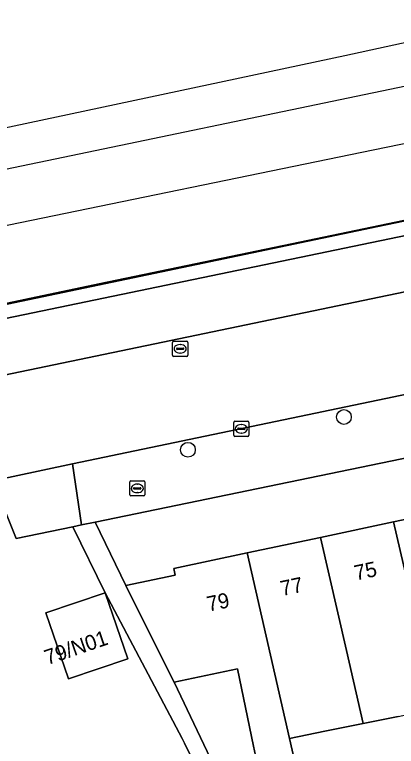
# Model space of a CAD drawing. Extents: x 162989 to 165008, y 383432 to 384338.
# Drawn here: x 163919.28 to 163944.51, y 384116.68 to 384165.09 of the extents above; entities that cross this region are included whole.
import ezdxf

# ---------------------------------------------------------------- set-up
doc = ezdxf.new("R2010")
doc.units = 0
for name, color, linetype in [('IMGEO_Boom', 7, 'Continuous'), ('IMGEO_Brandkraan', 7, 'Continuous'), ('IMGEO_Erf', 7, 'Continuous'), ('IMGEO_Geluidsscherm', 7, 'Continuous'), ('IMGEO_Groenvoorziening', 7, 'Continuous'), ('IMGEO_Haag', 7, 'Continuous'), ('IMGEO_Kolk', 7, 'Continuous'), ('IMGEO_Pand', 7, 'Continuous'), ('IMGEO_Pand_nummerreeks', 7, 'Continuous'), ('IMGEO_Rijbaan_lokaal_gesloten', 7, 'Continuous'), ('IMGEO_Rioolput', 7, 'Continuous'), ('IMGEO_Spoor', 7, 'Continuous'), ('IMGEO_Spoorbaan_halfverhard', 7, 'Continuous'), ('IMGEO_Voetpad_open', 7, 'Continuous')]:
    doc.layers.add(name, color=color, linetype=linetype)

msp = doc.modelspace()

# ---------------------------------------------------------------- linework, layer by layer
at = {"layer": 'IMGEO_Boom'}
for centre in [(163941.046, 384138.472), (163930.735, 384136.302)]:
    msp.add_circle(centre, 0.489, dxfattribs=at)
at = {"layer": 'IMGEO_Brandkraan'}
for p, q in [((163926.889, 384133.324), (163926.889, 384134.176)), ((163926.964, 384134.25), (163927.816, 384134.25)), ((163927.377, 384134.03), (163927.402, 384134.03)), ((163927.89, 384134.176), (163927.89, 384133.324)), ((163927.148, 384133.744), (163927.148, 384133.756)), ((163927.586, 384133.707), (163927.188, 384133.707)), ((163927.191, 384133.793), (163927.589, 384133.793)), ((163927.4, 384133.47), (163927.375, 384133.47)), ((163927.632, 384133.756), (163927.632, 384133.744)), ((163927.816, 384133.25), (163926.964, 384133.25))]:
    msp.add_line(p, q, dxfattribs=at)
for points in [[(163926.889, 384133.324), (163926.889, 384134.176)], [(163926.964, 384134.25), (163927.816, 384134.25)], [(163927.89, 384134.176), (163927.89, 384133.324)], [(163927.816, 384133.25), (163926.964, 384133.25)]]:
    msp.add_lwpolyline(points, dxfattribs=at)
for centre, radius, start, end in [((163926.966, 384134.174), 0.0765, 91.552, 178.448), ((163926.966, 384134.174), 0.0765, 91.552, 178.448), ((163927.814, 384134.174), 0.0765, 1.552, 88.448), ((163927.814, 384134.174), 0.0765, 1.552, 88.448), ((163927.188, 384133.753), 0.0403, 85.8775, 175.7526), ((163927.185, 384133.743), 0.0366, 178.938, 274.7102), ((163927.589, 384133.75), 0.043, 264.8664, 352.4533), ((163927.593, 384133.755), 0.0386, 1.7309, 96.639), ((163926.966, 384133.326), 0.0765, 181.552, 268.448), ((163926.966, 384133.326), 0.0765, 181.552, 268.448), ((163927.814, 384133.326), 0.0765, 271.552, 358.448), ((163927.814, 384133.326), 0.0765, 271.552, 358.448)]:
    msp.add_arc(centre, radius, start, end, dxfattribs=at)
for centre, major_axis, ratio, start_param, end_param in [((163927.376, 384133.75), (-0.387, 0.002), 0.722429, 4.712389, 7.853982), ((163927.401, 384133.75), (-0.39, 0.002), 0.717154, 1.570796, 4.712389)]:
    msp.add_ellipse(centre, major_axis=major_axis, ratio=ratio, start_param=start_param, end_param=end_param, dxfattribs=at)
at = {"layer": 'IMGEO_Erf'}
for points in [[(163949.177, 384132.553), (163954.118, 384133.598), (163959.059, 384134.642), (163958.806, 384135.902), (163958.304, 384138.407), (163954.262, 384137.638), (163924.604, 384131.515), (163926.626, 384127.328), (163929.903, 384128.02), (163929.809, 384128.46), (163934.649, 384129.483), (163939.492, 384130.507), (163944.334, 384131.53)], [(163925.265, 384126.849), (163926.756, 384122.485), (163922.841, 384121.148), (163921.35, 384125.512)]]:
    msp.add_lwpolyline(points, close=True, dxfattribs=at)
for points in [[(163944.693, 384087.722), (163943.187, 384090.664), (163940.668, 384096.069), (163940.042, 384097.411), (163938.387, 384100.469), (163933.086, 384111.619), (163931.815, 384114.219), (163930.51, 384116.89), (163930.356, 384117.204), (163925.265, 384126.849), (163923.141, 384131.213), (163919.387, 384130.435), (163918.639, 384132.305), (163909.406, 384130.442), (163905.997, 384128.384), (163911.891, 384112.19), (163917.32, 384097.768), (163932.033, 384058.943), (163947.096, 384019.256)], [(163944.64, 384118.661), (163942.328, 384118.204), (163939.784, 384117.7), (163937.446, 384117.206), (163938.282, 384113.537), (163935.867, 384112.987), (163935.081, 384116.706), (163934.004, 384121.804), (163929.817, 384120.934), (163939.604, 384100.356), (163940.409, 384100.553), (163940.568, 384099.756), (163944.833, 384100.609)]]:
    msp.add_lwpolyline(points, dxfattribs=at)
at = {"layer": 'IMGEO_Geluidsscherm'}
msp.add_lwpolyline([(163900.238, 384142.138), (163910.539, 384144.282), (163924.865, 384147.3), (163937.597, 384149.952), (163949.238, 384152.367)], dxfattribs=at)
at = {"layer": 'IMGEO_Groenvoorziening'}
for points in [[(163976.433, 384156.982), (163892.745, 384139.603), (163892.562, 384140.484), (163891.111, 384136.301), (163890.081, 384137.041), (163889.139, 384137.718), (163888.832, 384137.295), (163887.752, 384135.808), (163888.618, 384135.1), (163901.317, 384138.016), (163901.331, 384137.791), (163906.646, 384138.881), (163911.749, 384139.874), (163916.336, 384140.767), (163989.771, 384156.06)], [(163953.785, 384153.248), (163943.293, 384151.084), (163911.419, 384144.396), (163894.397, 384140.865), (163892.562, 384140.484), (163892.745, 384139.603), (163976.433, 384156.982)]]:
    msp.add_lwpolyline(points, dxfattribs=at)
at = {"layer": 'IMGEO_Haag'}
msp.add_lwpolyline([(163953.785, 384153.248), (163943.293, 384151.084), (163911.419, 384144.396), (163894.397, 384140.865), (163892.562, 384140.484), (163892.745, 384139.603), (163976.433, 384156.982)], dxfattribs=at)
at = {"layer": 'IMGEO_Kolk'}
for p, q in [((163933.767, 384137.267), (163933.767, 384138.119)), ((163933.842, 384138.193), (163934.694, 384138.193)), ((163934.069, 384137.736), (163934.467, 384137.736)), ((163934.255, 384137.973), (163934.28, 384137.973)), ((163934.768, 384138.119), (163934.768, 384137.267)), ((163934.026, 384137.687), (163934.026, 384137.699)), ((163934.464, 384137.65), (163934.066, 384137.65)), ((163934.278, 384137.413), (163934.253, 384137.413)), ((163934.51, 384137.699), (163934.51, 384137.687)), ((163934.694, 384137.193), (163933.842, 384137.193))]:
    msp.add_line(p, q, dxfattribs=at)
for points in [[(163933.767, 384137.267), (163933.767, 384138.119)], [(163933.842, 384138.193), (163934.694, 384138.193)], [(163934.768, 384138.119), (163934.768, 384137.267)], [(163934.694, 384137.193), (163933.842, 384137.193)]]:
    msp.add_lwpolyline(points, dxfattribs=at)
for centre, radius, start, end in [((163933.844, 384138.117), 0.0765, 91.552, 178.448), ((163933.844, 384138.117), 0.0765, 91.552, 178.448), ((163934.066, 384137.696), 0.0403, 85.8775, 175.7526), ((163934.471, 384137.698), 0.0386, 1.7309, 96.639), ((163934.692, 384138.117), 0.0765, 1.552, 88.448), ((163934.692, 384138.117), 0.0765, 1.552, 88.448), ((163933.844, 384137.269), 0.0765, 181.552, 268.448), ((163933.844, 384137.269), 0.0765, 181.552, 268.448), ((163934.063, 384137.686), 0.0366, 178.938, 274.7102), ((163934.467, 384137.693), 0.043, 264.8664, 352.4533), ((163934.692, 384137.269), 0.0765, 271.552, 358.448), ((163934.692, 384137.269), 0.0765, 271.552, 358.448)]:
    msp.add_arc(centre, radius, start, end, dxfattribs=at)
for centre, major_axis, ratio, start_param, end_param in [((163934.254, 384137.693), (-0.387, 0.002), 0.722429, 4.712389, 7.853982), ((163934.279, 384137.693), (-0.39, 0.002), 0.717154, 1.570796, 4.712389)]:
    msp.add_ellipse(centre, major_axis=major_axis, ratio=ratio, start_param=start_param, end_param=end_param, dxfattribs=at)
at = {"layer": 'IMGEO_Pand'}
for points in [[(163949.177, 384132.553), (163944.334, 384131.53), (163947.197, 384119.202), (163948.549, 384113.379), (163950.338, 384113.794), (163948.994, 384119.582), (163952.011, 384120.238), (163950.89, 384125.108)], [(163939.492, 384130.507), (163941.215, 384123.033), (163942.328, 384118.204), (163944.64, 384118.661), (163947.197, 384119.202), (163944.334, 384131.53)], [(163939.492, 384130.507), (163934.649, 384129.483), (163937.446, 384117.206), (163939.784, 384117.7), (163942.328, 384118.204), (163941.215, 384123.033)], [(163937.446, 384117.206), (163934.649, 384129.483), (163929.809, 384128.46), (163929.903, 384128.02), (163926.626, 384127.328), (163928.858, 384122.855), (163929.817, 384120.934), (163934.004, 384121.804), (163935.081, 384116.706), (163935.867, 384112.987), (163938.282, 384113.537)], [(163922.841, 384121.148), (163926.756, 384122.485), (163925.265, 384126.849), (163921.35, 384125.512)]]:
    msp.add_lwpolyline(points, close=True, dxfattribs=at)
at = {"layer": 'IMGEO_Rijbaan_lokaal_gesloten'}
msp.add_lwpolyline([(163923.113, 384135.366), (163960.826, 384143.251), (163966.926, 384144.526), (163982.743, 384147.834), (163986.464, 384148.612), (163997.553, 384150.93), (164000, 384151.442), (164001.293, 384151.706), (164009.768, 384153.438), (164008.393, 384160.13), (164000, 384158.405), (163989.771, 384156.06), (163916.336, 384140.767), (163911.749, 384139.874), (163913.038, 384133.253), (163917.195, 384134.125)], close=True, dxfattribs=at)
at = {"layer": 'IMGEO_Rioolput'}
for p, q in [((163929.725, 384142.558), (163929.725, 384143.41)), ((163929.8, 384143.484), (163930.652, 384143.484)), ((163930.213, 384143.264), (163930.238, 384143.264)), ((163930.726, 384143.41), (163930.726, 384142.558)), ((163929.984, 384142.978), (163929.984, 384142.99)), ((163930.422, 384142.941), (163930.024, 384142.941)), ((163930.027, 384143.027), (163930.425, 384143.027)), ((163930.236, 384142.704), (163930.211, 384142.704)), ((163930.468, 384142.99), (163930.468, 384142.978)), ((163930.652, 384142.484), (163929.8, 384142.484))]:
    msp.add_line(p, q, dxfattribs=at)
for points in [[(163929.725, 384142.558), (163929.725, 384143.41)], [(163929.8, 384143.484), (163930.652, 384143.484)], [(163930.726, 384143.41), (163930.726, 384142.558)], [(163930.652, 384142.484), (163929.8, 384142.484)]]:
    msp.add_lwpolyline(points, dxfattribs=at)
for centre, radius, start, end in [((163929.802, 384143.408), 0.0765, 91.552, 178.448), ((163929.802, 384143.408), 0.0765, 91.552, 178.448), ((163930.65, 384143.408), 0.0765, 1.552, 88.448), ((163930.65, 384143.408), 0.0765, 1.552, 88.448), ((163930.024, 384142.987), 0.0403, 85.8775, 175.7526), ((163930.021, 384142.977), 0.0366, 178.938, 274.7102), ((163930.425, 384142.984), 0.043, 264.8664, 352.4533), ((163930.429, 384142.989), 0.0386, 1.7309, 96.639), ((163929.802, 384142.56), 0.0765, 181.552, 268.448), ((163929.802, 384142.56), 0.0765, 181.552, 268.448), ((163930.65, 384142.56), 0.0765, 271.552, 358.448), ((163930.65, 384142.56), 0.0765, 271.552, 358.448)]:
    msp.add_arc(centre, radius, start, end, dxfattribs=at)
for centre, major_axis, ratio, start_param, end_param in [((163930.212, 384142.984), (-0.387, 0.002), 0.722429, 4.712389, 7.853982), ((163930.237, 384142.984), (-0.39, 0.002), 0.717154, 1.570796, 4.712389)]:
    msp.add_ellipse(centre, major_axis=major_axis, ratio=ratio, start_param=start_param, end_param=end_param, dxfattribs=at)
at = {"layer": 'IMGEO_Spoor'}
for points in [[(164788.231, 384335.773), (164684.182, 384314.23), (164649.743, 384306.978), (164549.034, 384286.117), (164446.504, 384264.637), (164353.435, 384245.24), (164284.243, 384230.902), (164214.646, 384216.358), (164173.585, 384207.909), (164102.605, 384193.066), (164031.754, 384178.409), (163810.752, 384132.353), (163673.071, 384103.86), (163574.904, 384083.455)], [(164789.572, 384332.389), (164775.58, 384329.429), (164644.744, 384302.256), (164570.629, 384286.722), (164345.336, 384239.894), (164220.116, 384213.747), (164092.662, 384187.275), (164071.527, 384182.957), (163942.979, 384156.119), (163900.983, 384147.477), (163806.025, 384127.659), (163575.669, 384079.775)]]:
    msp.add_lwpolyline(points, dxfattribs=at)
at = {"layer": 'IMGEO_Spoorbaan_halfverhard'}
for points in [[(164064.865, 384189.352), (163941.114, 384162.363), (163913.021, 384156.381)], [(163911.419, 384144.396), (163943.293, 384151.084), (163953.785, 384153.248)]]:
    msp.add_lwpolyline(points, dxfattribs=at)
at = {"layer": 'IMGEO_Voetpad_open'}
for points in [[(163958.304, 384138.407), (163958.806, 384135.902), (163959.059, 384134.642), (163959.347, 384134.703), (163962.536, 384135.377), (163964.941, 384135.885), (163963.186, 384139.88), (163961.855, 384142.91), (163960.94, 384142.716), (163960.826, 384143.251), (163923.113, 384135.366), (163923.697, 384131.328), (163924.604, 384131.515), (163954.262, 384137.638)], [(163923.113, 384135.366), (163917.195, 384134.125), (163918.639, 384132.305), (163919.387, 384130.435), (163923.141, 384131.213), (163923.697, 384131.328)]]:
    msp.add_lwpolyline(points, close=True, dxfattribs=at)
msp.add_lwpolyline([(163946.672, 384086.586), (163942.846, 384094.132), (163940.691, 384098.645), (163940.196, 384099.682), (163940.568, 384099.756), (163940.409, 384100.553), (163939.604, 384100.356), (163929.817, 384120.934), (163928.858, 384122.855), (163926.626, 384127.328), (163924.604, 384131.515), (163923.697, 384131.328), (163923.141, 384131.213), (163925.265, 384126.849), (163930.356, 384117.204), (163930.51, 384116.89), (163931.815, 384114.219), (163933.086, 384111.619), (163938.387, 384100.469), (163940.042, 384097.411), (163940.668, 384096.069), (163943.187, 384090.664), (163944.693, 384087.722)], dxfattribs=at)

# ---------------------------------------------------------------- texts
at = {"layer": 'IMGEO_Pand_nummerreeks'}
for s, rotation, p in [('75', 11.9341, (163941.841, 384127.651)), ('77', 11.9341, (163936.959, 384126.62)), ('79', 11.9341, (163932.099, 384125.592)), ('79/N01', 18.8384, (163921.455, 384122.055))]:
    msp.add_text(s, height=1, rotation=rotation, dxfattribs=at).set_placement(p)

doc.saveas('drawing.dxf')
